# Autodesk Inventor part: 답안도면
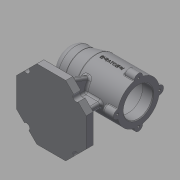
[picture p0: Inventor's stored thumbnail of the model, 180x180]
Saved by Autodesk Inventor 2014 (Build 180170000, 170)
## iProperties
Created: 2021-01
Part Number: 답안도면
Material: Generic
Document SubType Name: Modeling
Designer: kh
Density: 1 g/cm^3
Appearance: Default
Mass: 232.753 g
Surface Area: 617.741 cm^2
Volume: 232.753 cm^3
Author: kh
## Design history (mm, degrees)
sketch "Sketch1"
  geometry: L1 (0, 0)-(100, 0); L2 (100, 0)-(100, 30); L3 (100, 30)-(40, 30); L4 (40, 30)-(20, 25); L5 (20, 25)-(0, 25); L6 (0, 25)-(0, 0); L7 (100, 21)-(85, 21); L8 (85, 21)-(85, 24); L9 (85, 24)-(43, 24); L10 (43, 24)-(43, 21); L11 (43, 21)-(31, 21); L12 (31, 21)-(31, 17.5); L13 (31, 17.5)-(13, 17.5); L14 (13, 17.5)-(13, 16); L15 (13, 16)-(9, 16); L16 (9, 16)-(9, 10.5); L17 (9, 10.5)-(6, 10.5); L18 (6, 10.5)-(6, 0)
  constraints: 36 end point, 11 parallel, 4 perpendicular, 2 point on line, 1 collinear, 1 horizontal
  dimensions: "d0" = 100 distance of L1.start L1.end; "d1" = 60 diameter of L3 L1; "d2" = 50 diameter of L5 L1; "d3" = 20 distance of L4.end L5.end; "d4" = 40 horizontal distance of L5.end L3.end; "d6" = 42 diameter of L7 L1; "d7" = 48 diameter of L9 L1; "d8" = 42 diameter of L11 L1; "d9" = 35 diameter of L13 L1; "d10" = 32 diameter of L15 L1; "d11" = 21 diameter of L17 L1; "d12" = 3 distance of L16.end L17.end; "d13" = 4 distance of L14.end L15.end; "d14" = 18 distance of L12.end L13.end; "d15" = 12 distance of L10.end L11.end; "d16" = 42 distance of L8.end L9.end; "d17" = 15 distance of L7.start L7.end
revolve "Revolution1" stored, may be unused: angle "d5" = 90 deg
revolve "Revolution2" stored, may be unused: angle "d18" = 90 deg
workplane "Work Plane1"
sketch "Sketch2" dims "d20" = 100
  geometry: L1 (-100, 30)-(-100, -30) reference; L2 (0, 25)-(0, -25) reference; L3 (-40, 30)-(-40, -30) reference; L4 (-100, 30)-(-100, -30) reference; L5 (-40, -30)-(-100, -30) reference; L6 (-40, 30)-(-100, 30) reference; L7 (0, 0)-(-50, 0); L8 (-70.711, -50)-(-100, -20.711); L9 (-100, -20.711)-(-100, 20.711); L10 (-100, 20.711)-(-70.711, 50); L11 (-70.711, 50)-(-29.289, 50); L12 (-29.289, 50)-(0, 20.711); L13 (0, 20.711)-(0, -20.711); L14 (0, -20.711)-(-29.289, -50); L15 (-29.289, -50)-(-70.711, -50); L16 (-50, 0)-(-50, -50)
  constraints: 20 end point, 1 coincident, 1 midpoint, 1 parallel, 1 vertical, 1 vertical alignment, 19 other
  dimensions: "d21" = 50 distance of L7.start L7.end
extrude "Extrusion1" join sketch "Sketch2" distance "d22" = 10; taper "d23" = 0 deg
sketch "Sketch3"
  geometry: L1 (100, 20.711)-(100, -20.711) reference; L2 (100, -20.711)-(70.711, -50) reference; L3 (70.711, -50)-(29.289, -50) reference; L4 (29.289, -50)-(0, -20.711) reference; L5 (0, -20.711)-(0, 20.711) reference; L6 (0, 20.711)-(29.289, 50) reference; L7 (29.289, 50)-(70.711, 50) reference; L8 (70.711, 50)-(100, 20.711) reference; L9 (62, 4)-(77, 4); L10 (77, 4)-(77, -4); L11 (77, -4)-(62, -4); L12 (62, -4)-(62, 4); L13 (0, 0)-(77, 0)
  constraints: 10 end point, 2 horizontal, 2 parallel, 1 midpoint, 1 perpendicular
  dimensions: "d24" = 8 distance of L9.end L10.end; "d25" = 23 distance from line of L1 L13.end; "d26" = 15 distance of L9.start L9.end
extrude "Extrusion2" join sketch "Sketch3" stored distance "d27" = 0; taper "d28" = 0 deg
sketch "Sketch4"
  geometry: L1 (0, -25)-(0, 25) reference; L2 (0, 25)-(20, 25) reference; L3 (20, 25)-(40, 30) reference; L4 (40, 30)-(100, 30) reference; L5 (100, 30)-(100, 21) reference; L6 (100, 21)-(85, 21) reference; L7 (85, 21)-(85, 24) reference; L8 (85, 24)-(43, 24) reference; L9 (43, 24)-(43, 21) reference; L10 (43, 21)-(31, 21) reference; L11 (31, 21)-(31, 17.5) reference; L12 (31, 17.5)-(13, 17.5) reference; L13 (13, 17.5)-(13, 16) reference; L14 (13, 16)-(9, 16) reference; L15 (9, 16)-(9, 10.5) reference; L16 (9, 10.5)-(6, 10.5) reference; L17 (6, 10.5)-(6, -10.5) reference; L18 (6, -10.5)-(9, -10.5) reference; L19 (9, -10.5)-(9, -16) reference; L20 (9, -16)-(13, -16) reference; L21 (13, -16)-(13, -17.5) reference; L22 (13, -17.5)-(31, -17.5) reference; L23 (31, -17.5)-(31, -21) reference; L24 (31, -21)-(43, -21) reference; L25 (43, -21)-(43, -24) reference; L26 (43, -24)-(85, -24) reference; L27 (85, -24)-(85, -21) reference; L28 (85, -21)-(100, -21) reference; L29 (100, -21)-(100, -30) reference; L30 (100, -30)-(77, -30) reference; L31 (77, -30)-(77, -65) reference; L32 (77, -65)-(100, -65) reference; L33 (100, -65)-(100, -75) reference; L34 (100, -75)-(0, -75) reference; L35 (0, -75)-(0, -65) reference; L36 (0, -65)-(62, -65) reference; L37 (62, -65)-(62, -30) reference; L38 (62, -30)-(40, -30) reference; L39 (40, -30)-(20, -25) reference; L40 (20, -25)-(0, -25) reference; L41 (23, -65)-(27.653, -41.063); 1 further point
  constraints: 2 end point, 1 point on line
  dimensions: "d29" = 23 distance of L41.start L35.end; "d30" = 101 deg angle of L36 L41
feature "Rib1" sketch "Sketch4" dims "d31" = 1, "d32" = 8, "d33" = 0, "d34" = 0, "d35" = 1, "d36" = 1
workplane "Work Plane2"
sketch "Sketch5"
  geometry: L1 (-65, 50)-(-65, 4) reference; L2 (-65, 4)-(-29.732, 4) reference; L3 (-29.732, -4)-(-65, -4) reference; L4 (-65, -4)-(-65, -50) reference; L5 (-65, -50)-(-75, -50) reference; L6 (-75, -50)-(-75, 50) reference; L7 (-75, 50)-(-65, 50) reference; L8 (-65, 35)-(-42.933, 26.968); L9 (-65, -35)-(-36.274, -24.545); C1 r 24 at (0, 0) reference; A1 r 30 centre (0, 0) between (-29.732, -4) and (-29.732, 4) reference; 1 further point
  constraints: 4 end point, 2 point on line
  dimensions: "d37" = 15 distance of L8.start L1.start; "d38" = 15 distance of L4.end L9.start; "d39" = 110 deg angle of L8 L1; "d40" = 110 deg angle of L4 L9
  node "Project Cut Edges3"
feature "Rib2" dims "d41" = 1, "d42" = 8, "d43" = 0, "d44" = 0, "d45" = 1, "d46" = 1
feature "Rib3" dims "d47" = 1, "d48" = 8, "d49" = 0, "d50" = 0, "d51" = 1, "d52" = 1
sketch "Sketch6"
  geometry: L1 (0, 0)-(0, 30); C1 r 21 at (0, 0) reference; C2 r 6 at (0, 30); 2 further points
  constraints: 2 end point, 1 centre point, 1 vertical, 1 vertical alignment, 1 other
  dimensions: "d53" = 12 diameter of C2
extrude "Extrusion3" join sketch "Sketch6" distance "d54" = 16; taper "d55" = 0 deg
hole "Hole1" diameter "d58" = 3.242; stored, may be unused: countersink angle "d62" = 90 deg, drill point angle "d64" = 118 deg; dims "d56" = 10, "d57" = 10, "d59" = 8, "d60" = 4, "d61" = 2, "d63" = 10
pattern_circular "Circular Pattern1" dims angle "d66" = 360 deg
sketch "Sketch7"
  geometry: L1 (70.711, -50)-(29.289, -50) reference; L2 (29.289, -50)-(0, -20.711) reference; L3 (0, -20.711)-(0, 20.711) reference; L4 (0, 20.711)-(29.289, 50) reference; L5 (29.289, 50)-(70.711, 50) reference; L6 (70.711, 50)-(100, 20.711) reference; L7 (100, 20.711)-(100, -20.711) reference; L8 (100, -20.711)-(70.711, -50) reference; L9 (0, 0)-(100, 0); L10 (50, 50)-(50, -50); L11 (14.645, -35.355)-(85.355, 35.355); L12 (14.645, 35.355)-(85.355, -35.355); C1 r 4.5 at (14.645, -35.355); C2 r 4.5 at (85.355, 35.355); C3 r 4.5 at (85.355, -35.355); C4 r 4.5 at (14.645, 35.355); 2 further points
  constraints: 9 midpoint, 8 end point, 4 centre point, 4 coincident, 1 point on line
  dimensions: "d69" = 9 diameter of C1; "d70" = 9 diameter of C2; "d71" = 9 diameter of C3; "d73" = 9 diameter of C4
extrude "Extrusion4" cut sketch "Sketch7" stored distance "d74" = 16; taper "d75" = 0 deg
fillet "Fillet1" dims "d76" = 10
fillet "Fillet2" dims "d77" = 3
fillet "Fillet3" dims "d78" = 3
fillet "Fillet4" dims "d79" = 3
fillet "Fillet5" dims "d80" = 3
fillet "Fillet6" dims "d81" = 3
fillet "Fillet7" dims "d82" = 1
fillet "Fillet8" dims "d83" = 1
fillet "Fillet9" dims "d84" = 3
fillet "Fillet10" dims "d85" = 0.3
chamfer "Chamfer1" distance "d86" = 1; stored, may be unused: second distance "d87" = 2, angle "d88" = 45 deg
workplane "Work Plane3"
sketch "Sketch8"
  geometry: L1 (-24.592, 2.402)-(8.592, 2.402); L2 (8.592, 2.402)-(8.592, -2.402); L3 (8.592, -2.402)-(-24.592, -2.402); L4 (-24.592, -2.402)-(-24.592, 2.402); L5 (-24.592, 0)-(8.592, 0); L6 (-8, 2.402)-(-8, -2.402); L7 (30, 6.771)-(30, 29.226) reference; 1 further point
  constraints: 4 end point, 4 midpoint, 1 horizontal alignment, 2 other
  dimensions: "d89" = 38 distance between parallel lines of L7 L6
emboss "Emboss1" sketch "Sketch8" dims "d0" = 100, "d1" = 60, "d2" = 50, "d3" = 20, "d4" = 40, "d6" = 42, "d7" = 48, "d8" = 42, "d9" = 35, "d10" = 32, "d11" = 21, "d12" = 3, "d13" = 4, "d14" = 18, "d15" = 12, "d16" = 42, "d17" = 15, "d90" = 0.5, "d91" = 0
body "Solid1"
node "Projected Loop1"
node "Projected Loop2"
node "Projected Loop3"
node "Project Cut Edges1"
node "Project Cut Edges2"
other parameters: "d19" = -75
